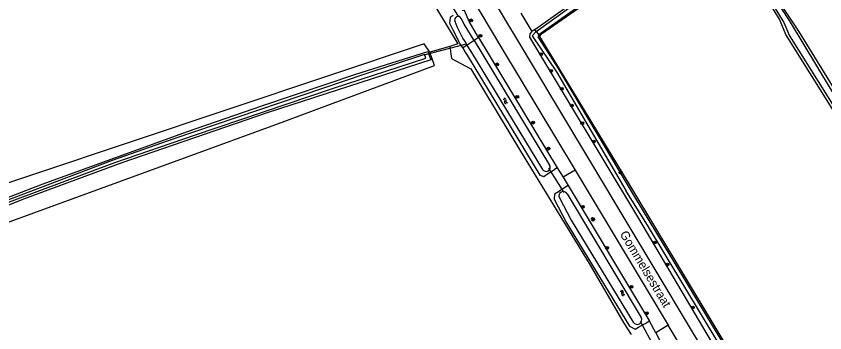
# Model space of a CAD drawing. Extents: x 137000 to 140001, y 403500 to 406000.
# Drawn here: x 139240.9 to 139469.8, y 404120.8 to 404210.4 of the extents above; entities that cross this region are included whole.
import ezdxf

# ---------------------------------------------------------------- set-up
doc = ezdxf.new("R2010")
doc.units = 0
for name, color, linetype in [('gg-anno-openbare ruimte label', 7, 'Continuous'), ('gg-knt-bronhoudergrens', 7, 'Continuous'), ('gg-knt-verharding', 7, 'Continuous'), ('gg-kntw-bovenkant insteek waterloop', 7, 'Continuous'), ('gg-kntw-waterlijn', 7, 'Continuous'), ('gg-kwrk-duiker nz buis', 7, 'Continuous'), ('gt-grn-groengrens', 7, 'Continuous'), ('gt-grn-groengrens NZ', 7, 'Continuous'), ('gt-grn-vlakafsluiter', 7, 'Continuous'), ('gt-grn-weggrens', 7, 'Continuous'), ('gt-symb-boom', 7, 'Continuous'), ('gt-symb-lichtmast', 7, 'Continuous'), ('gt-symb-watersymbool', 7, 'Continuous')]:
    doc.layers.add(name, color=color, linetype=linetype)

# ---------------------------------------------------------------- blocks, each defined once
blk = doc.blocks.new('gt0-BOOM')
at = {"layer": 'gt-symb-boom'}
for radius in [0.4, 0.2]:
    blk.add_circle((0, 0), radius, dxfattribs=at)
blk = doc.blocks.new('gt0-WA')
at = {"layer": 'gt-symb-watersymbool'}
for centre, start, end in [((-0.32, 0.02), 28.0725, 151.9275), ((0.43, 0.42), 208.0725, 331.9275), ((-0.32, -0.43), 28.0725, 151.9275), ((0.43, -0.03), 208.0725, 331.9275)]:
    blk.add_arc(centre, 0.425, start, end, dxfattribs=at)
blk = doc.blocks.new('gt0-LMAST')
at = {"layer": 'gt-symb-lichtmast'}
for p, q in [((-0.18, 0.17), (-0.45, 0.44)), ((-0.01, 0.25), (-0.01, 0.62)), ((0.17, 0.17), (0.44, 0.44)), ((-0.26, 0), (-0.63, 0)), ((-0.18, -0.18), (-0.45, -0.45)), ((-0.01, -0.25), (-0.01, -0.63)), ((0.44, -0.45), (0.17, -0.18)), ((0.24, 0), (0.62, 0))]:
    blk.add_line(p, q, dxfattribs=at)
blk.add_circle((-0.01, 0), 0.25, dxfattribs=at)

msp = doc.modelspace()

# ---------------------------------------------------------------- linework, layer by layer
at = {"layer": 'gg-knt-bronhoudergrens'}
for p, q in [((139313.24, 404289.83), (139365.92, 404202.56)), ((139365.92, 404202.56), (139363.62, 404201.87)), ((139363.62, 404201.87), (139357.99, 404200.18))]:
    msp.add_line(p, q, dxfattribs=at)
for points in [[(139357.99, 404200.18), (139356.37, 404202.59), (139190.44, 404147.13), (139161.26, 404191), (139310.93, 404284.69), (139307.73, 404289.53)], [(139153.3, 404120.79), (139215.08, 404143.56), (139314.37, 404179.73), (139359.32, 404196.47), (139357.99, 404200.18)], [(139363.62, 404201.87), (139364.08, 404198.39), (139369.62, 404195.55), (139383.68, 404172.19), (139403.36, 404139.96), (139412.9, 404123.55), (139414.99, 404120.37)]]:
    msp.add_lwpolyline(points, dxfattribs=at)
at = {"layer": 'gg-knt-verharding'}
for p, q in [((139380.34, 404207.8), (139365.18, 404233.19)), ((139381.92, 404205.17), (139380.34, 404207.8)), ((139487.48, 404029.17), (139381.92, 404205.17)), ((139399.06, 404166.86), (139425.42, 404122.96)), ((139456.55, 404071.12), (139425.42, 404122.96))]:
    msp.add_line(p, q, dxfattribs=at)
msp.add_lwpolyline([(139337.94, 404269.03), (139378.26, 404201.49), (139399.06, 404166.86)], dxfattribs=at)
at = {"layer": 'gg-kntw-bovenkant insteek waterloop'}
for p, q in [((139387.68, 404206.64), (139386.87, 404206.06)), ((139388.09, 404206.08), (139387.68, 404206.64)), ((139389.11, 404204.68), (139388.79, 404205.11)), ((139414.71, 404162.5), (139389.11, 404204.68)), ((139371.79, 404204.36), (139394.03, 404167.48)), ((139391.27, 404165.77), (139393.25, 404166.99)), ((139394.03, 404167.48), (139393.25, 404166.99)), ((139397.15, 404162.51), (139396.41, 404162.01)), ((139397.15, 404162.51), (139420.13, 404124.12)), ((139420.13, 404124.12), (139419.16, 404123.56))]:
    msp.add_line(p, q, dxfattribs=at)
for points in [[(139387.68, 404206.64), (139396.48, 404212.89), (139438.63, 404243.47)], [(139389.11, 404204.68), (139389.55, 404205.37), (139413.96, 404222.41), (139439.45, 404240.88), (139439.7, 404241.23)], [(139462.35, 404206.12), (139486.61, 404166.69), (139495.97, 404152.33), (139495.87, 404151.34), (139494.75, 404150.61), (139493.4, 404150.24), (139492.84, 404150.82), (139492.2, 404151.72), (139458.75, 404205.22), (139456.9, 404209.55), (139448.86, 404222.72), (139448.84, 404223.23), (139449.26, 404223.76), (139450.13, 404223.96), (139450.7, 404223.62), (139462.35, 404206.12)], [(139371.79, 404204.36), (139369.07, 404208.86), (139367.79, 404212.01), (139367.16, 404211.88)], [(139364.55, 404210.55), (139363.76, 404210.06), (139363.52, 404208.4)], [(139363.52, 404208.4), (139364.37, 404206.74), (139366.05, 404203.44)], [(139386.87, 404206.06), (139386.78, 404206), (139386.25, 404205.41), (139386.17, 404204.42), (139417.02, 404153.17), (139447.37, 404101.81), (139487.93, 404035.35), (139490.55, 404030.97)], [(139367.27, 404201.42), (139366.5, 404202.7), (139366.05, 404203.44)], [(139185.14, 404146.32), (139186.71, 404147.52), (139192.19, 404141.15), (139248.24, 404162.83), (139289.43, 404177.79), (139310.72, 404185.15), (139337.08, 404194), (139357.37, 404200.42), (139358.27, 404198.03), (139311.9, 404183.02), (139270.79, 404168.89), (139242.96, 404158.67), (139191.72, 404138.02), (139185.14, 404146.32)], [(139367.27, 404201.42), (139368.01, 404200.21), (139368.54, 404199.33), (139389.06, 404165.42)], [(139389.06, 404165.42), (139390.22, 404165.07), (139391.27, 404165.77)], [(139396.41, 404162.01), (139395.92, 404161.7), (139394.42, 404160.75), (139393.22, 404160)], [(139456.9, 404092.22), (139445.66, 404110.93), (139414.71, 404162.5)], [(139393.22, 404160), (139393.13, 404158.65), (139396.67, 404151.93), (139414.5, 404122.69), (139416.12, 404121.87), (139417.06, 404122.45)], [(139417.06, 404122.45), (139418.52, 404123.22), (139419.16, 404123.56)]]:
    msp.add_lwpolyline(points, dxfattribs=at)
at = {"layer": 'gg-kntw-waterlijn'}
for p, q in [((139370.53, 404203.54), (139391.88, 404168.26)), ((139396.83, 404160.12), (139417.79, 404125.11))]:
    msp.add_line(p, q, dxfattribs=at)
for points in [[(139388.09, 404206.08), (139397.44, 404212.79), (139438.66, 404242.65), (139439.38, 404242.44), (139439.7, 404241.85), (139439.03, 404241.2), (139410.28, 404220.39), (139388.79, 404205.11)], [(139493.13, 404151.52), (139493.71, 404151.05), (139494.61, 404151.33), (139495.11, 404151.82), (139495.35, 404152.44), (139479.68, 404176.18), (139459.8, 404209.14), (139451.24, 404222.16), (139450.1, 404223.2), (139449.5, 404223.14), (139449.37, 404222.88), (139458.17, 404208.61), (139459.8, 404204.86), (139481.58, 404170.15), (139493.13, 404151.52)], [(139370.53, 404203.54), (139367.72, 404208.18), (139366.85, 404209.78)], [(139368.53, 404202.24), (139367.78, 404203.48), (139367.36, 404204.17), (139365.71, 404207.42), (139365.11, 404208.87)], [(139388.09, 404206.08), (139386.92, 404204.81), (139393.79, 404194.63), (139413.42, 404161.09)], [(139388.79, 404205.11), (139388.51, 404204.55), (139394.25, 404195.63), (139415.86, 404159.33), (139426.22, 404142.34), (139446.98, 404107.72), (139471.44, 404066.61), (139492.1, 404031.98), (139492.05, 404031.82), (139491.91, 404031.55), (139491.71, 404031.45), (139491.27, 404031.39), (139452.28, 404096.48), (139445.13, 404108.88), (139419.89, 404150.83), (139413.42, 404161.09)], [(139389.91, 404167.03), (139369.82, 404200.11), (139369.29, 404200.99), (139368.53, 404202.24)], [(139186.08, 404146.23), (139191.87, 404139.07), (139239.8, 404158.15), (139268.87, 404168.99), (139291.37, 404176.78), (139330.68, 404190.06), (139356.82, 404198.56), (139356.5, 404199.53), (139339.62, 404194.04), (139285.58, 404175.69), (139268.12, 404169.53), (139237.52, 404158.01), (139191.93, 404140.08), (139186.6, 404146.64), (139186.08, 404146.23)], [(139394.65, 404158.98), (139397.98, 404152.67), (139415.56, 404123.84)]]:
    msp.add_lwpolyline(points, dxfattribs=at)
for centre, radius, start, end in [((139365.98, 404209.33), 0.981, 27.6372, 207.6079), ((139390.89, 404167.64), 1.16, 212.1099, 32.1469), ((139395.74, 404159.55), 1.23, 27.739, 207.6805), ((139416.67, 404124.48), 1.28, 209.8554, 29.8225)]:
    msp.add_arc(centre, radius, start, end, dxfattribs=at)
at = {"layer": 'gg-kwrk-duiker nz buis'}
for p, q in [((139366.18, 404210.17), (139361.82, 404217.27)), ((139368.23, 404202.53), (139356.29, 404199.33)), ((139396.01, 404160.48), (139391.65, 404167.37)), ((139421.5, 404116.85), (139417.55, 404124.02))]:
    msp.add_line(p, q, dxfattribs=at)
at = {"layer": 'gt-grn-groengrens'}
msp.add_line((139383.76, 404211.26), (139386.87, 404206.06), dxfattribs=at)
at = {"layer": 'gt-grn-groengrens NZ'}
for p, q in [((139394.03, 404167.48), (139395.69, 404164.84)), ((139395.69, 404164.84), (139397.15, 404162.51)), ((139421.9, 404120.84), (139420.13, 404124.12)), ((139421.9, 404120.84), (139422.98, 404118.86))]:
    msp.add_line(p, q, dxfattribs=at)
at = {"layer": 'gt-grn-vlakafsluiter'}
for p, q in [((139388.09, 404206.08), (139388.79, 404205.11)), ((139370.53, 404203.54), (139368.53, 404202.24)), ((139371.79, 404204.36), (139370.53, 404203.54)), ((139368.53, 404202.24), (139367.27, 404201.42))]:
    msp.add_line(p, q, dxfattribs=at)
at = {"layer": 'gt-grn-weggrens'}
for p, q in [((139399.06, 404166.86), (139395.69, 404164.84)), ((139425.42, 404122.96), (139421.9, 404120.84))]:
    msp.add_line(p, q, dxfattribs=at)

# ---------------------------------------------------------------- block references
at = {"layer": 'gt-symb-boom'}
for p in [(139369.65, 404209.21), (139372.27, 404204.82), (139389.48, 404199.65), (139377.05, 404196.76), (139392.29, 404194.9), (139395.33, 404189.85), (139382.73, 404187.58), (139398.18, 404185.15), (139387.24, 404180.29), (139401.13, 404180.11), (139404.38, 404174.91), (139391.55, 404172.93), (139411.96, 404166.18), (139401.27, 404156.48), (139408.12, 404144.88), (139421.66, 404146.37), (139425.21, 404140.12), (139415.04, 404133.82), (139432.42, 404127.96), (139419.38, 404126.34)]:
    msp.add_blockref('gt0-BOOM', p, dxfattribs=at)
at = {"layer": 'gt-symb-lichtmast'}
msp.add_blockref('gt0-LMAST', (139404.16, 404152.95), dxfattribs=at)
at = {"layer": 'gt-symb-watersymbool', "rotation": 126.9958977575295}
for p in [(139379.36, 404186.34), (139412.52, 404132.04)]:
    msp.add_blockref('gt0-WA', p, dxfattribs=at)

# ---------------------------------------------------------------- texts
at = {"layer": 'gg-anno-openbare ruimte label'}
msp.add_text('Gommelsestraat', height=2.5, rotation=301, dxfattribs=at).set_placement((139411.64, 404148.77))

doc.saveas('drawing.dxf')
